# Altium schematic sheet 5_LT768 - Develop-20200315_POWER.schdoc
size 805 x 261 mm
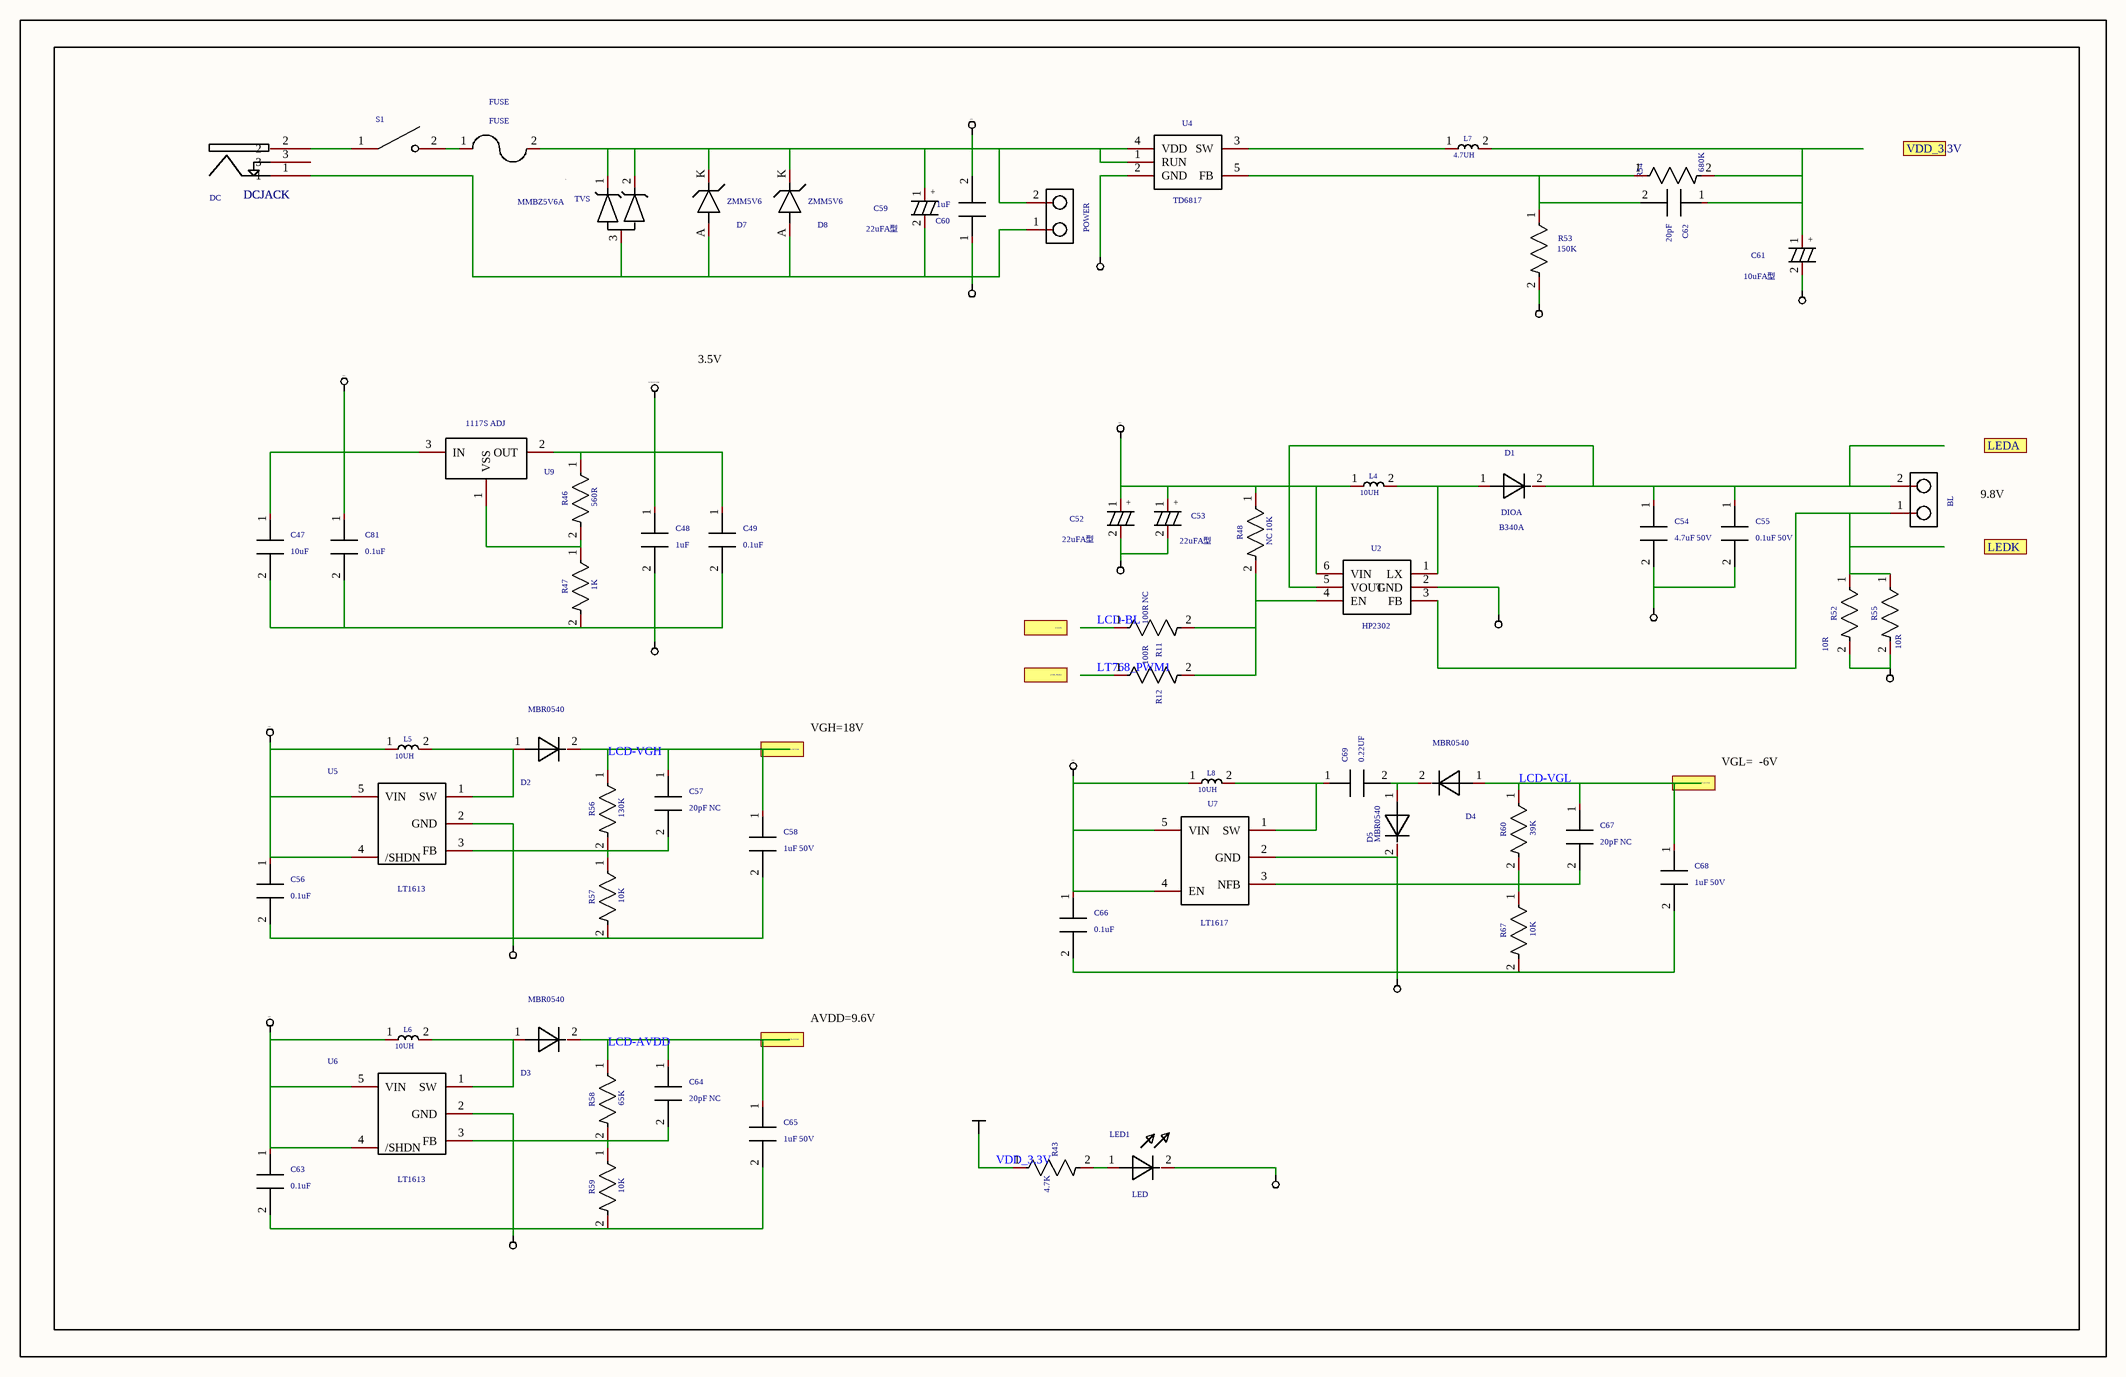
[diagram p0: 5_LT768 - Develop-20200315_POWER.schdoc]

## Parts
BL  COM2  (value not drawn)
C47  10uF
C48  1uF
C49  0.1uF
C52  value 22uFA型  (hidden comment: 22uF/A型)
C53  value 22uFA型  (hidden comment: 22uF/A型)
C54  4.7uF 50V
C55  0.1uF 50V
C56  0.1uF
C57  20pF NC
C58  1uF 50V
C59  value 22uFA型  (hidden comment: 22uF/A型)
C60  1uF
C61  value 10uFA型  (hidden comment: 10uF/A型)
C62  20pF
C63  0.1uF
C64  20pF NC
C65  1uF 50V
C66  0.1uF
C67  20pF NC
C68  1uF 50V
C69  0.22UF
C81  0.1uF
D1  B340A
D2  MBR0540
D3  MBR0540
D4  MBR0540
D5  MBR0540
D7  ZMM5V6
D8  ZMM5V6
DC  DCJACK
FUSE  FUSE
L4  10UH
L5  10UH
L6  10UH
L7  4.7UH
L8  10UH
LED1  LED
POWER  COM2  (value not drawn)
R11  100R NC
R12  100R
R43  4.7K
R46  560R
R47  1K
R48  NC 10K
R52  10R
R53  150K
R54  680K
R55  10R
R56  130K
R57  10K
R58  65K
R59  10K
R60  39K
R67  10K
S1  SW-SPST-NO  (value not drawn)
TVS  MMBZ5V6A
U2  HP2302
U4  TD6817
U5  LT1613
U6  LT1613
U7  LT1617
U9  value 1117S ADJ  (hidden comment: AMS1117)

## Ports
LCD-AVDD (in), LCD-BL (in), LCD-VGH (in), LCD-VGL (in), LEDA (out), LEDK (out), LT768_PWM1 (in), VDD_3.3V (out)

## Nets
+5V: C47.1 C52.1 C53.1 C56.1 C59.1 C60.2 C63.1 C66.1 C81.1 D7.K D8.K FUSE.2 L4.1 L5.1 L6.1 L8.1 POWER.2 R48.1 TVS.1 TVS.2 U2.6(VIN) U4.1(RUN) U4.4(VDD) U5.4(/SHDN) U5.5(VIN) U6.4(/SHDN) U6.5(VIN) U7.4(EN) U7.5(VIN) U9.3(IN)
GND: C47.2 C48.2 C49.2 C52.2 C53.2 C54.2 C55.2 C56.2 C58.2 C59.2 C60.1 C61.2 C63.2 C65.2 C66.2 C68.2 C81.2 D5.2 D7.A D8.A DC.1 LED1.2 POWER.1 R47.2 R52.2 R53.2 R55.2 R57.2 R59.2 R67.2 TVS.3 U2.2(GND) U4.2(GND) U5.2(GND) U6.2(GND) U7.2(GND)
LCD-VCOM: C48.1 C49.1 R46.1 U9.2(OUT)
VDD_3.3V: R43.1
LCD-AVDD: C64.1 C65.1 D3.2 R58.1 ; port LCD-AVDD
LCD-BL: R11.1
LCD-VGH: C57.1 C58.1 D2.2 R56.1 ; port LCD-VGH
LCD-VGL: C67.1 C68.1 D4.1 R60.1 ; port LCD-VGL
LT768_PWM1: R12.1
NetBL_1: BL.1 R52.1 R55.1 U2.3(FB)
NetBL_2: BL.2 C54.1 C55.1 D1.2 U2.5(VOUT)
NetC57_2: C57.2 R56.2 R57.1 U5.3(FB)
NetC61_1: C61.1 C62.1 L7.2 R54.2
NetC62_2: C62.2 R53.1 R54.1 U4.5(FB)
NetC64_2: C64.2 R58.2 R59.1 U6.3(FB)
NetC67_2: C67.2 R60.2 R67.1 U7.3(NFB)
NetC69_1: C69.1 L8.2 U7.1(SW)
NetC69_2: C69.2 D4.2 D5.1
NetD1_1: D1.1 L4.2 U2.1(LX)
NetD2_1: D2.1 L5.2 U5.1(SW)
NetD3_1: D3.1 L6.2 U6.1(SW)
NetDC_2: DC.2 S1.1
NetFUSE_1: FUSE.1 S1.2
NetL7_1: L7.1 U4.3(SW)
NetLED1_1: LED1.1 R43.2
NetR11_2: R11.2 R12.2 R48.2 U2.4(EN)
NetR46_2: R46.2 R47.1 U9.1(VSS)

Not connected (* = marked no-connect by the designer): DC 3

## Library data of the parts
BL = COM2: Connector; Symbol: CON2_PIN; Add into BOM: yes; PCB DECAL: HA01
C47 C48 C54 = CAP0603: Capacitor; PART DESC: CERAMIC CAP.0.1UF/50V +/-20% 0603; PART NO: 014104BZ2503; PART NUMBER: 022-109600310-00; Symbol: CAP; Add into BOM: yes; _: 0.0103; PCB DECAL: C0805
C49 C55-C58 C60 C62-C69 C81 = CAP0603: Capacitor; PART DESC: CERAMIC CAP.0.1UF/50V +/-20% 0603; PART NO: 014104BZ2503; PART NUMBER: 022-109600310-00; Symbol: CAP; Add into BOM: yes; _: 0.0103; PCB DECAL: C0603
C52 C53 C59 C61 = E.CAP: Capacitor; Symbol: E.CAPC; Add into BOM: yes; PCB DECAL: 3528
D1-D5 = DIOA: Diode; Add into BOM: yes; PCB DECAL: DO-214
D7 D8 = DIODE-ZENER: Symbol: DIOZ-H; Add into BOM: yes; Sim_Analog_Order: Model$; PCB DECAL: TA/SMA
DC = DCJACK: Connector; Add into BOM: yes; PCB DECAL: JACK/DC6
FUSE = FUSE: Add into BOM: yes; PCB DECAL: FUSE/SMB
L4-L6 L8 = 47UH-CHOKE: Industance; PART DESC: COIL 47uH-CHOKE; PART NUMBER: 037-001000001-00; Symbol: FB220; Add into BOM: yes; PCB DECAL: IND8A
L7 = 47UH-CHOKE: Industance; PART DESC: COIL 47uH-CHOKE; PART NUMBER: 037-001000001-00; Symbol: FB220; Add into BOM: yes; PCB DECAL: IND6B
LED1 = LED: Add into BOM: yes
POWER = COM2: Header; Symbol: CON2_PIN; Add into BOM: yes; PCB DECAL: JACK/2.54MM
R11 R12 R43 R46-R48 R53 R54 R56-R60 R67 = RES: Resistance; Symbol: RESZ-V; Add into BOM: yes; PCB DECAL: R0603
R52 R55 = RES: Resistance; Symbol: RESZ-V; Add into BOM: yes; PCB DECAL: R0805
S1 = SW-SPST-NO: SWITCH; Add into BOM: yes; Sim_Analog_Order: Model$; Value: ???; PCB DECAL: TURN
TVS = TVS2: TVS; Add into BOM: yes; PCB DECAL: SOT-23-1
U2 = HP2302: IC; Symbol: SOP6; Add into BOM: yes; PCB DECAL: SOT23-6
U4 = TD6817: IC; Add into BOM: yes; PCB DECAL: SOT23-5
U5 U6 = LT1613: IC; Add into BOM: yes; PCB DECAL: SOT23-5
U7 = LT1617: IC; Add into BOM: yes; PCB DECAL: SOT23-5
U9 = AMS1117: IC; Part_Type: LDO; Add into BOM: yes; PCB DECAL: SOT223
